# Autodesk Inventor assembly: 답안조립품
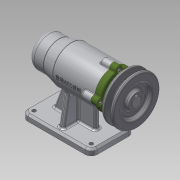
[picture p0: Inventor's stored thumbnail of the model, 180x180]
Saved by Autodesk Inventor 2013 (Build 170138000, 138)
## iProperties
Created: 2019-07
Part Number: 답안조립품
Document SubType Name: Assembly
Designer: Administrator
Author: Administrator
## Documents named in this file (12)
- C:\Users\Administrator\Desktop\490704V1032\답안조립품.iam
- C:\Users\Administrator\Desktop\490704V1032\본체.ipt
- C:\Users\Administrator\Desktop\490704V1032\V벨트풀리.ipt
- C:\Users\Administrator\Desktop\490704V1032\멈춤나사 M3.ipt
- C:\Users\Administrator\Desktop\490704V1032\베어링 6004.ipt
- C:\Users\Administrator\Desktop\490704V1032\베어링 51202.ipt
- C:\Users\Administrator\Desktop\490704V1032\볼트 M4.ipt
- C:\Users\Administrator\Desktop\490704V1032\어댑터슬리브.ipt
- C:\Users\Administrator\Desktop\490704V1032\오일 실.ipt
- C:\Users\Administrator\Desktop\490704V1032\축.ipt
- C:\Users\Administrator\Desktop\490704V1032\커버.ipt
- C:\Users\Administrator\Desktop\490704V1032\키 5 x 5 x 16.ipt
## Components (1 placed, 1 different names)
1. V벨트풀리:1
